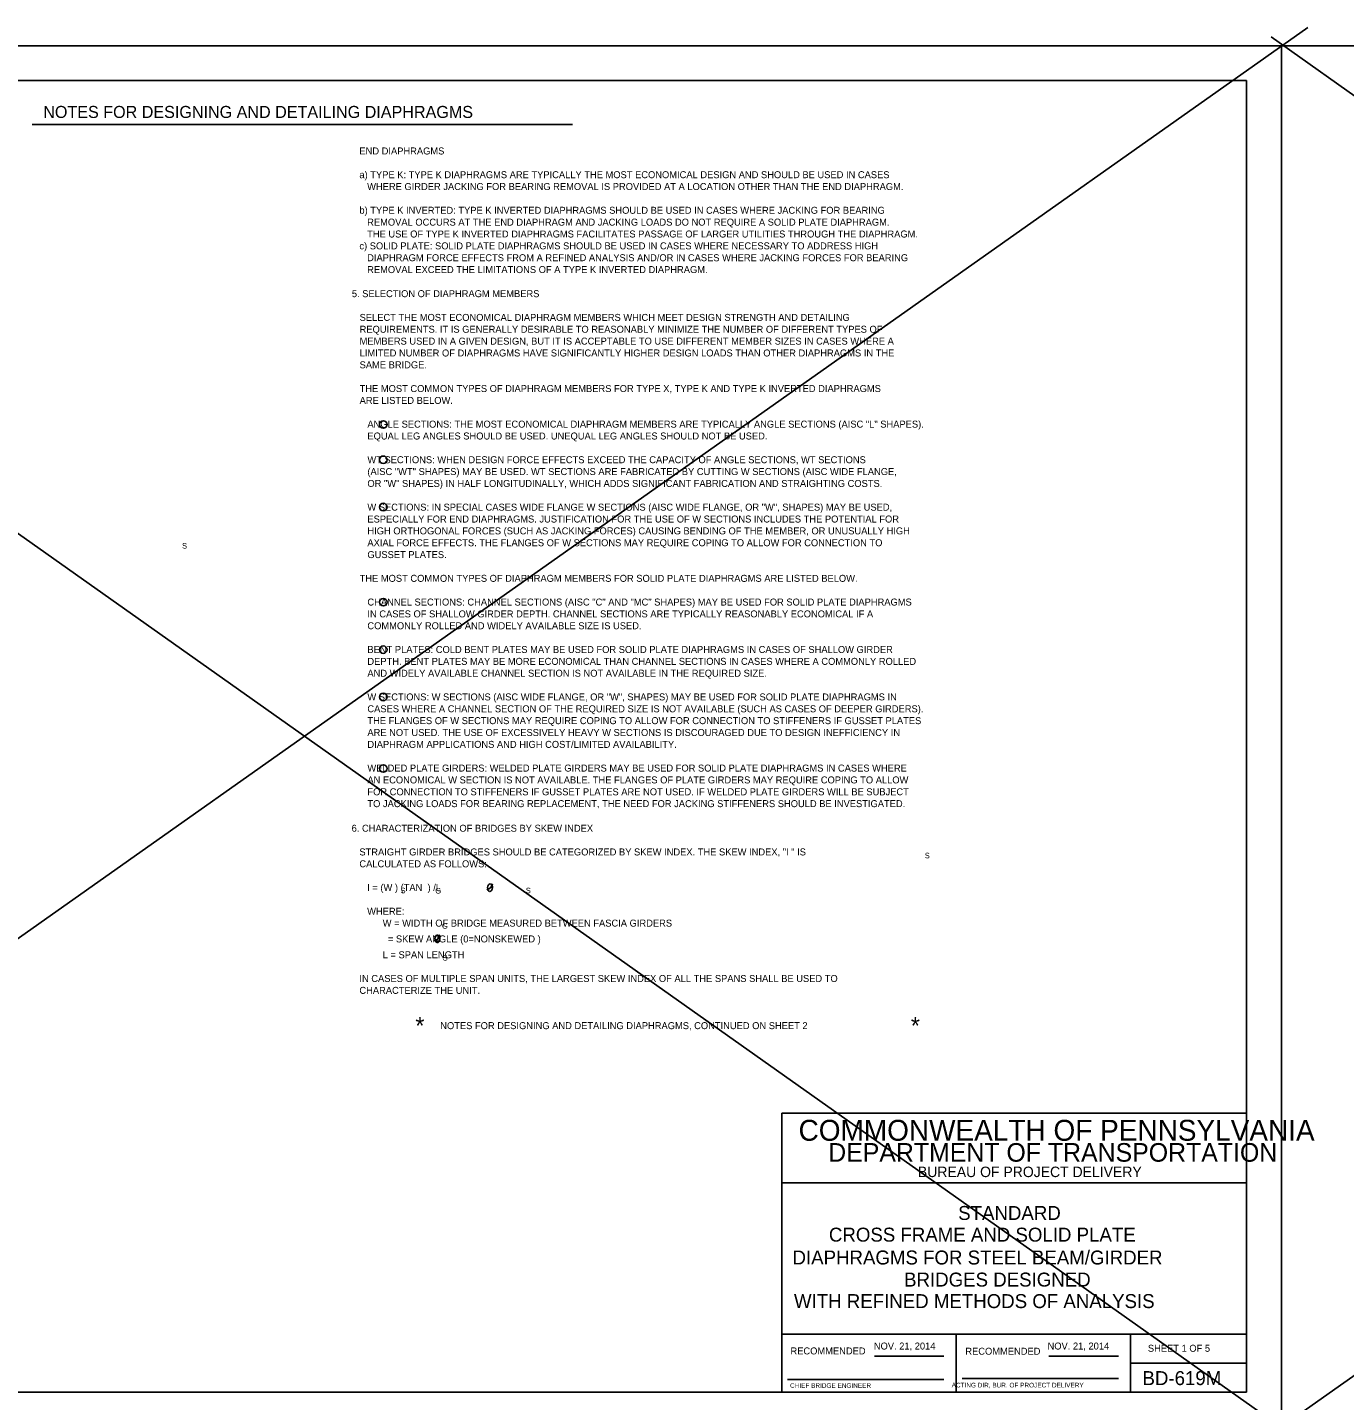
# Model space of a CAD drawing. Extents: x 634656 to 641360, y 298715 to 301183.
# Drawn here: x 634968 to 635535, y 299924 to 300515 of the extents above; entities that cross this region are included whole.
import ezdxf

# ---------------------------------------------------------------- set-up
doc = ezdxf.new("R2010")
doc.units = 0
for name, color, linetype in [('1', 7, 'Continuous'), ('2', 7, 'Continuous'), ('PLT-BNDY', 7, 'Continuous')]:
    doc.layers.add(name, color=color, linetype=linetype)

msp = doc.modelspace()

# ---------------------------------------------------------------- linework, layer by layer
at = {"layer": '1'}
for p, q in [((634656.46, 299906.13), (635518.79, 300514.83)), ((635497.46, 299906.13), (636359.79, 300514.83)), ((634661.92, 300510.77), (635521.53, 299902.94)), ((635502.92, 300510.77), (636362.53, 299902.94))]:
    msp.add_line(p, q, dxfattribs=at)
for centre in [(635121.02, 300344.09), (635121.02, 300328.95), (635121.02, 300308.61), (635121.02, 300267.73), (635121.02, 300247.28), (635121.02, 300226.94), (635121.02, 300196.18)]:
    msp.add_circle(centre, 1.61, dxfattribs=at)
for centre in [(635164.95, 300147.12), (635142.31, 300125.15)]:
    msp.add_arc(centre, 3.13, 281.30867, 349.81327, dxfattribs=at)
for centre in [(635166.95, 300144.91), (635144.31, 300122.94)]:
    msp.add_ellipse(centre, major_axis=(0.07, 1.63), ratio=0.651229, dxfattribs=at)
at = {"layer": '2'}
for p, q in [((634706.42, 300491.99), (635492.42, 300491.99)), ((635492.42, 299927.99), (635492.42, 300491.99)), ((634969.94, 300473.11), (635202.43, 300473.11)), ((635292.42, 300047.99), (635292.42, 299927.99)), ((635492.42, 300047.99), (635292.42, 300047.99)), ((635492.42, 299927.99), (635492.42, 300047.99)), ((635492.42, 300017.99), (635292.42, 300017.99)), ((635492.42, 299952.99), (635292.42, 299952.99)), ((635367.42, 299927.99), (635367.42, 299952.99)), ((635442.42, 299952.99), (635442.42, 299927.99)), ((635292.42, 299927.99), (635292.42, 299948.99)), ((635332.38, 299943.49), (635362.15, 299943.49)), ((635407.38, 299943.49), (635437.29, 299943.49)), ((635442.42, 299940.49), (635492.42, 299940.49)), ((635294.92, 299933.49), (635362.15, 299933.49)), ((635370.04, 299933.86), (635437.29, 299933.86)), ((635492.42, 299927.99), (634706.42, 299927.99)), ((635292.42, 299927.99), (635492.42, 299927.99))]:
    msp.add_line(p, q, dxfattribs=at)
at = {"layer": 'PLT-BNDY'}
for points in [[(634666.42, 300506.99), (635507.42, 300506.99), (635507.42, 299912.99), (634666.42, 299912.99)], [(635507.42, 300506.99), (636348.42, 300506.99), (636348.42, 299912.99), (635507.42, 299912.99)]]:
    msp.add_lwpolyline(points, close=True, dxfattribs=at)

# ---------------------------------------------------------------- texts
at = {"layer": '1'}
for s, height, p in [('NOTES FOR DESIGNING AND DETAILING DIAPHRAGMS', 5.1838, (634974.76, 300475.91)), ('   END DIAPHRAGMS', 2.9999, (635107.41, 300460.22)), ('   a) TYPE K: TYPE K DIAPHRAGMS ARE TYPICALLY THE MOST ECONOMICAL DESIGN AND SHOULD BE USED IN CASES', 2.9999, (635107.41, 300450.02)), ('      WHERE GIRDER JACKING FOR BEARING REMOVAL IS PROVIDED AT A LOCATION OTHER THAN THE END DIAPHRAGM.', 2.99987, (635107.41, 300444.92)), ('   b) TYPE K INVERTED: TYPE K INVERTED DIAPHRAGMS SHOULD BE USED IN CASES WHERE JACKING FOR BEARING', 2.9999, (635107.41, 300434.72)), ('      REMOVAL OCCURS AT THE END DIAPHRAGM AND JACKING LOADS DO NOT REQUIRE A SOLID PLATE DIAPHRAGM.', 2.9999, (635107.41, 300429.62)), ('      THE USE OF TYPE K INVERTED DIAPHRAGMS FACILITATES PASSAGE OF LARGER UTILITIES THROUGH THE DIAPHRAGM.', 2.99987, (635107.41, 300424.52)), ('   c) SOLID PLATE: SOLID PLATE DIAPHRAGMS SHOULD BE USED IN CASES WHERE NECESSARY TO ADDRESS HIGH', 2.9999, (635107.41, 300419.42)), ('      DIAPHRAGM FORCE EFFECTS FROM A REFINED ANALYSIS AND/OR IN CASES WHERE JACKING FORCES FOR BEARING', 2.99987, (635107.41, 300414.32)), ('      REMOVAL EXCEED THE LIMITATIONS OF A TYPE K INVERTED DIAPHRAGM.', 2.9999, (635107.41, 300409.22)), ('5. SELECTION OF DIAPHRAGM MEMBERS', 2.9999, (635107.51, 300398.86)), ('   SELECT THE MOST ECONOMICAL DIAPHRAGM MEMBERS WHICH MEET DESIGN STRENGTH AND DETAILING', 2.9999, (635107.51, 300388.66)), ('   REQUIREMENTS. IT IS GENERALLY DESIRABLE TO REASONABLY MINIMIZE THE NUMBER OF DIFFERENT TYPES OF', 2.9999, (635107.51, 300383.56)), ('   MEMBERS USED IN A GIVEN DESIGN, BUT IT IS ACCEPTABLE TO USE DIFFERENT MEMBER SIZES IN CASES WHERE A', 2.99987, (635107.51, 300378.46)), ('   LIMITED NUMBER OF DIAPHRAGMS HAVE SIGNIFICANTLY HIGHER DESIGN LOADS THAN OTHER DIAPHRAGMS IN THE', 2.9999, (635107.51, 300373.36)), ('   SAME BRIDGE.', 2.9999, (635107.51, 300368.26)), ('   THE MOST COMMON TYPES OF DIAPHRAGM MEMBERS FOR TYPE X, TYPE K AND TYPE K INVERTED DIAPHRAGMS', 2.9999, (635107.51, 300358.06)), ('   ARE LISTED BELOW.', 2.9999, (635107.51, 300352.96)), ('      ANGLE SECTIONS: THE MOST ECONOMICAL DIAPHRAGM MEMBERS ARE TYPICALLY ANGLE SECTIONS (AISC "L" SHAPES).', 2.99987, (635107.51, 300342.76)), ('      EQUAL LEG ANGLES SHOULD BE USED. UNEQUAL LEG ANGLES SHOULD NOT BE USED.', 2.9999, (635107.51, 300337.66)), ('      WT SECTIONS: WHEN DESIGN FORCE EFFECTS EXCEED THE CAPACITY OF ANGLE SECTIONS, WT SECTIONS', 2.9999, (635107.51, 300327.46)), ('      (AISC "WT" SHAPES) MAY BE USED. WT SECTIONS ARE FABRICATED BY CUTTING W SECTIONS (AISC WIDE FLANGE, ', 2.99987, (635107.51, 300322.36)), ('      OR "W" SHAPES) IN HALF LONGITUDINALLY, WHICH ADDS SIGNIFICANT FABRICATION AND STRAIGHTING COSTS.', 2.99987, (635107.51, 300317.26)), ('      W SECTIONS: IN SPECIAL CASES WIDE FLANGE W SECTIONS (AISC WIDE FLANGE, OR "W", SHAPES) MAY BE USED,', 2.99987, (635107.51, 300307.06)), ('      ESPECIALLY FOR END DIAPHRAGMS. JUSTIFICATION FOR THE USE OF W SECTIONS INCLUDES THE POTENTIAL FOR', 2.99987, (635107.51, 300301.96)), ('      HIGH ORTHOGONAL FORCES (SUCH AS JACKING FORCES) CAUSING BENDING OF THE MEMBER, OR UNUSUALLY HIGH', 2.99987, (635107.51, 300296.86)), ('S', 2.4, (635034.47, 300290.75)), ('      AXIAL FORCE EFFECTS. THE FLANGES OF W SECTIONS MAY REQUIRE COPING TO ALLOW FOR CONNECTION TO', 2.9999, (635107.51, 300291.76)), ('      GUSSET PLATES.', 2.9999, (635107.51, 300286.66)), ('   THE MOST COMMON TYPES OF DIAPHRAGM MEMBERS FOR SOLID PLATE DIAPHRAGMS ARE LISTED BELOW.', 2.9999, (635107.51, 300276.46)), ('      CHANNEL SECTIONS: CHANNEL SECTIONS (AISC "C" AND "MC" SHAPES) MAY BE USED FOR SOLID PLATE DIAPHRAGMS', 2.99987, (635107.51, 300266.26)), ('      IN CASES OF SHALLOW GIRDER DEPTH. CHANNEL SECTIONS ARE TYPICALLY REASONABLY ECONOMICAL IF A', 2.9999, (635107.51, 300261.16)), ('      COMMONLY ROLLED AND WIDELY AVAILABLE SIZE IS USED.', 2.9999, (635107.51, 300256.06)), ('      BENT PLATES: COLD BENT PLATES MAY BE USED FOR SOLID PLATE DIAPHRAGMS IN CASES OF SHALLOW GIRDER', 2.99987, (635107.51, 300245.86)), ('      DEPTH. BENT PLATES MAY BE MORE ECONOMICAL THAN CHANNEL SECTIONS IN CASES WHERE A COMMONLY ROLLED', 2.99987, (635107.51, 300240.76)), ('      AND WIDELY AVAILABLE CHANNEL SECTION IS NOT AVAILABLE IN THE REQUIRED SIZE.', 2.9999, (635107.51, 300235.66)), ('      W SECTIONS: W SECTIONS (AISC WIDE FLANGE, OR "W", SHAPES) MAY BE USED FOR SOLID PLATE DIAPHRAGMS IN', 2.99987, (635107.51, 300225.46)), ('      THE FLANGES OF W SECTIONS MAY REQUIRE COPING TO ALLOW FOR CONNECTION TO STIFFENERS IF GUSSET PLATES', 2.99987, (635107.51, 300215.26)), ('      CASES WHERE A CHANNEL SECTION OF THE REQUIRED SIZE IS NOT AVAILABLE (SUCH AS CASES OF DEEPER GIRDERS).', 2.99987, (635107.51, 300220.36)), ('      ARE NOT USED. THE USE OF EXCESSIVELY HEAVY W SECTIONS IS DISCOURAGED DUE TO DESIGN INEFFICIENCY IN', 2.99987, (635107.51, 300210.16)), ('      DIAPHRAGM APPLICATIONS AND HIGH COST/LIMITED AVAILABILITY.', 2.9999, (635107.51, 300205.06)), ('      WELDED PLATE GIRDERS: WELDED PLATE GIRDERS MAY BE USED FOR SOLID PLATE DIAPHRAGMS IN CASES WHERE', 2.99987, (635107.51, 300194.87)), ('      AN ECONOMICAL W SECTION IS NOT AVAILABLE. THE FLANGES OF PLATE GIRDERS MAY REQUIRE COPING TO ALLOW', 2.99987, (635107.51, 300189.77)), ('      FOR CONNECTION TO STIFFENERS IF GUSSET PLATES ARE NOT USED. IF WELDED PLATE GIRDERS WILL BE SUBJECT', 2.99987, (635107.51, 300184.67)), ('      TO JACKING LOADS FOR BEARING REPLACEMENT, THE NEED FOR JACKING STIFFENERS SHOULD BE INVESTIGATED.', 2.99987, (635107.51, 300179.57)), ('6. CHARACTERIZATION OF BRIDGES BY SKEW INDEX', 2.9999, (635107.41, 300169)), ('   STRAIGHT GIRDER BRIDGES SHOULD BE CATEGORIZED BY SKEW INDEX. THE SKEW INDEX, "I " IS ', 2.9999, (635107.41, 300158.8)), ('S', 2.4, (635353.99, 300157.55)), ('   CALCULATED AS FOLLOWS:', 2.9999, (635107.41, 300153.7)), ('      I = (W ) (TAN  ) /L', 2.9999, (635107.41, 300143.5)), ('S', 2.4, (635128.46, 300142.52)), ('G', 2.4, (635143.4, 300142.43)), ('S', 2.4, (635182.36, 300142.52)), ('      WHERE:', 2.9999, (635107.41, 300133.3)), ('            W = WIDTH OF BRIDGE MEASURED BETWEEN FASCIA GIRDERS', 2.9999, (635107.41, 300128.2)), ('G', 2.4, (635146.26, 300127.31)), ('              = SKEW ANGLE (0=NONSKEWED )', 2.9999, (635107.41, 300121.4)), ('            L = SPAN LENGTH', 2.9999, (635107.41, 300114.59)), ('S', 2.4, (635146.57, 300113.59)), ('   IN CASES OF MULTIPLE SPAN UNITS, THE LARGEST SKEW INDEX OF ALL THE SPANS SHALL BE USED TO', 2.9999, (635107.41, 300104.39)), ('   CHARACTERIZE THE UNIT.', 2.9999, (635107.41, 300099.29)), ('*', 7.5, (635134.83, 300081.85)), ('*', 7.5, (635347.97, 300081.85)), ('NOTES FOR DESIGNING AND DETAILING DIAPHRAGMS, CONTINUED ON SHEET 2', 2.9999, (635145.54, 300084.11)), ('NOV. 21, 2014', 2.9956, (635332.06, 299946.35)), ('NOV. 21, 2014', 2.9956, (635406.79, 299946.35))]:
    msp.add_text(s, height=height, dxfattribs=at).set_placement(p)
at = {"layer": '2'}
for s, height, p in [('COMMONWEALTH OF PENNSYLVANIA', 9, (635299.67, 300036.11)), ('DEPARTMENT OF TRANSPORTATION', 8.0002, (635312.42, 300027.11)), ('BUREAU OF PROJECT DELIVERY', 4.5, (635351.01, 300020.49)), ('STANDARD', 6, (635368.34, 300002.06)), ('CROSS FRAME AND SOLID PLATE', 6, (635312.73, 299992.74)), ('DIAPHRAGMS FOR STEEL BEAM/GIRDER', 6, (635297.07, 299982.91)), ('BRIDGES DESIGNED', 6, (635345.07, 299973.42)), ('WITH REFINED METHODS OF ANALYSIS', 6, (635297.7, 299964.16)), ('SHEET 1 OF 5', 3, (635449.94, 299945.38)), ('BD-619M', 6, (635447.62, 299931.05)), ('CHIEF BRIDGE ENGINEER', 2.0002, (635296.01, 299929.86)), ('   ACTING DIR, BUR. OF PROJECT DELIVERY', 2.0002, (635363.24, 299930.04))]:
    msp.add_text(s, height=height, dxfattribs=at).set_placement(p)
for p in [(635296.19, 299944.24), (635371.41, 299944.11)]:
    msp.add_text('RECOMMENDED', height=3, rotation=360, dxfattribs=at).set_placement(p)

doc.saveas('drawing.dxf')
